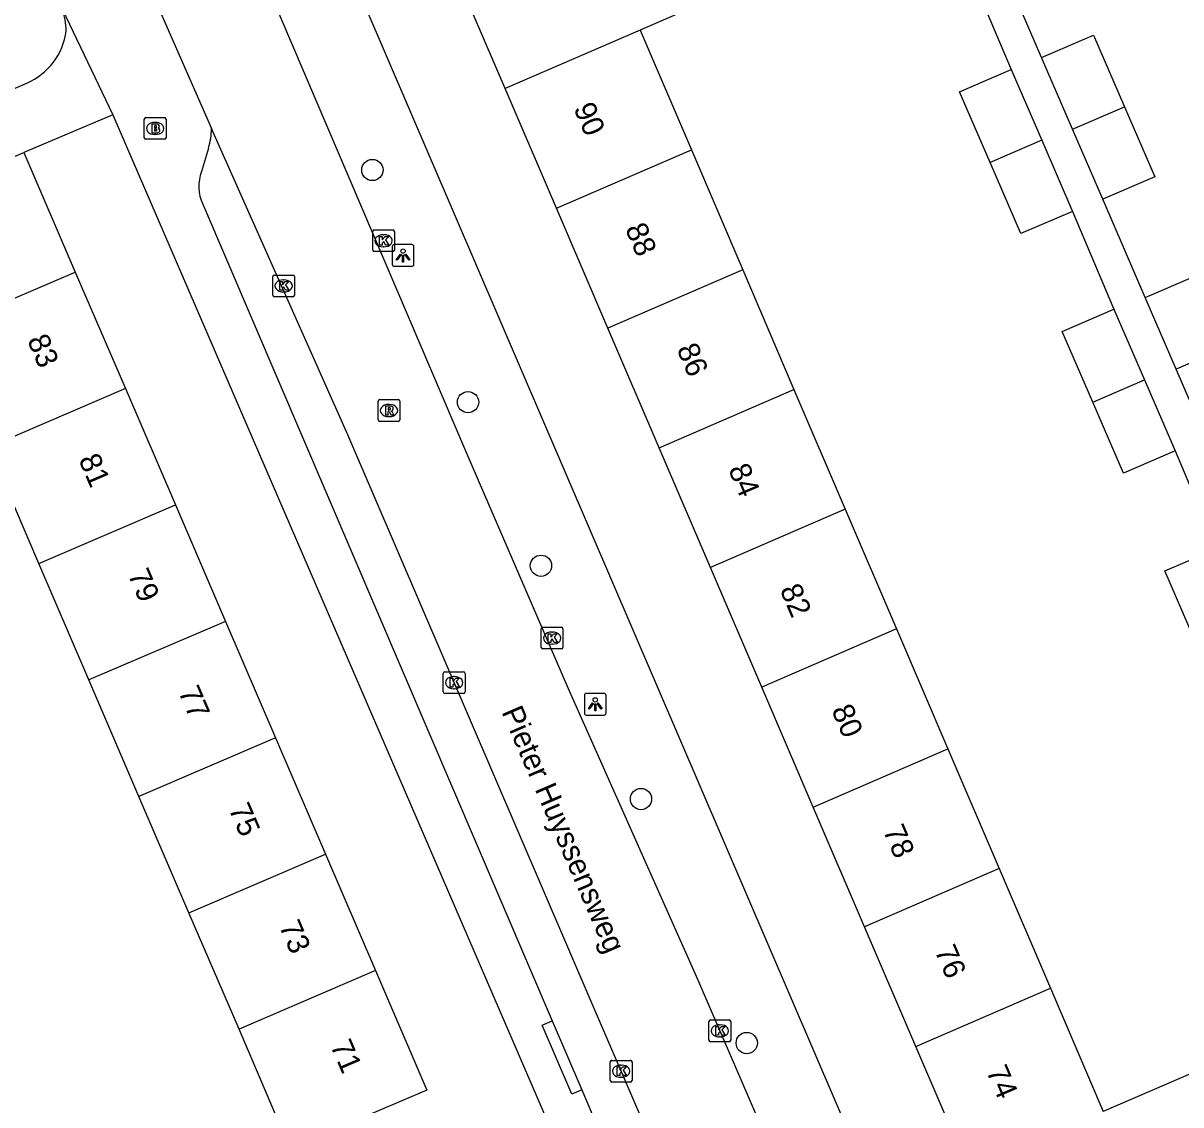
# Model space of a CAD drawing. Extents: x 159353 to 160616, y 385893 to 387321.
# Drawn here: x 159638.3 to 159691.6, y 386358.8 to 386408.6 of the extents above; entities that cross this region are included whole.
import ezdxf

# ---------------------------------------------------------------- set-up
doc = ezdxf.new("R2010")
doc.units = 0
for name, color, linetype in [('IMGEO_Boom', 7, 'Continuous'), ('IMGEO_Brandkraan', 7, 'Continuous'), ('IMGEO_Kolk', 7, 'Continuous'), ('IMGEO_Lichtpunt', 7, 'Continuous'), ('IMGEO_Openbare_ruimte_label', 7, 'Continuous'), ('IMGEO_Pand', 7, 'Continuous'), ('IMGEO_Pand_nummerreeks', 7, 'Continuous'), ('IMGEO_Rijbaan_lokaal_open', 7, 'Continuous'), ('IMGEO_Rioolput', 7, 'Continuous'), ('IMGEO_Voetpad_open', 7, 'Continuous')]:
    doc.layers.add(name, color=color, linetype=linetype)

msp = doc.modelspace()

# ---------------------------------------------------------------- linework, layer by layer
at = {"layer": 'IMGEO_Boom'}
for centre in [(159654.404, 386401.84), (159658.804, 386391.157), (159662.157, 386383.63), (159666.757, 386372.899), (159671.622, 386361.672)]:
    msp.add_circle(centre, 0.489, dxfattribs=at)
at = {"layer": 'IMGEO_Brandkraan'}
for p, q in [((159643.914, 386403.325), (159643.914, 386404.177)), ((159643.989, 386404.251), (159644.841, 386404.251)), ((159644.402, 386404.031), (159644.427, 386404.031)), ((159644.915, 386404.177), (159644.915, 386403.325)), ((159644.425, 386403.471), (159644.4, 386403.471)), ((159644.841, 386403.251), (159643.989, 386403.251))]:
    msp.add_line(p, q, dxfattribs=at)
for points in [[(159643.914, 386403.325), (159643.914, 386404.177)], [(159643.989, 386404.251), (159644.841, 386404.251)], [(159644.262, 386403.951), (159644.262, 386403.551), (159644.475, 386403.551)], [(159644.493, 386403.951), (159644.262, 386403.951)], [(159644.915, 386404.177), (159644.915, 386403.325)], [(159644.441, 386403.87), (159644.387, 386403.87), (159644.387, 386403.794)], [(159644.387, 386403.794), (159644.44, 386403.794)], [(159644.449, 386403.718), (159644.387, 386403.718), (159644.387, 386403.637)], [(159644.387, 386403.637), (159644.449, 386403.637)], [(159644.841, 386403.251), (159643.989, 386403.251)]]:
    msp.add_lwpolyline(points, dxfattribs=at)
for centre, radius, start, end in [((159643.991, 386404.175), 0.0765, 91.552, 178.448), ((159643.991, 386404.175), 0.0765, 91.552, 178.448), ((159644.497, 386403.806), 0.145, 59.4692, 91.5367), ((159644.522, 386403.853), 0.0922, 285.5137, 58.1501), ((159644.839, 386404.175), 0.0765, 1.552, 88.448), ((159644.839, 386404.175), 0.0765, 1.552, 88.448), ((159644.442, 386403.832), 0.0379, 267.8285, 90.9355), ((159644.45, 386403.677), 0.0404, 269.8759, 90.5077), ((159644.481, 386403.802), 0.251, 268.6676, 293.5347), ((159644.527, 386403.661), 0.105, 301.3115, 78.989), ((159643.991, 386403.327), 0.0765, 181.552, 268.448), ((159643.991, 386403.327), 0.0765, 181.552, 268.448), ((159644.839, 386403.327), 0.0765, 271.552, 358.448), ((159644.839, 386403.327), 0.0765, 271.552, 358.448)]:
    msp.add_arc(centre, radius, start, end, dxfattribs=at)
for centre, major_axis, ratio, start_param, end_param in [((159644.401, 386403.751), (-0.387, 0.002), 0.722429, 4.712389, 7.853982), ((159644.426, 386403.751), (-0.39, 0.002), 0.717154, 1.570796, 4.712389)]:
    msp.add_ellipse(centre, major_axis=major_axis, ratio=ratio, start_param=start_param, end_param=end_param, dxfattribs=at)
at = {"layer": 'IMGEO_Kolk'}
for p, q in [((159654.493, 386399.083), (159655.345, 386399.083)), ((159654.418, 386398.157), (159654.418, 386399.009)), ((159654.906, 386398.863), (159654.931, 386398.863)), ((159655.419, 386399.009), (159655.419, 386398.157)), ((159655.345, 386398.083), (159654.493, 386398.083)), ((159654.929, 386398.303), (159654.904, 386398.303)), ((159649.898, 386397.006), (159650.75, 386397.006)), ((159649.823, 386396.08), (159649.823, 386396.932)), ((159650.311, 386396.786), (159650.336, 386396.786)), ((159650.824, 386396.932), (159650.824, 386396.08)), ((159650.75, 386396.006), (159649.898, 386396.006)), ((159650.334, 386396.226), (159650.309, 386396.226)), ((159662.169, 386379.877), (159662.169, 386380.729)), ((159662.244, 386380.803), (159663.096, 386380.803)), ((159662.657, 386380.583), (159662.682, 386380.583)), ((159663.17, 386380.729), (159663.17, 386379.877)), ((159662.68, 386380.023), (159662.655, 386380.023)), ((159663.096, 386379.803), (159662.244, 386379.803)), ((159657.664, 386377.827), (159657.664, 386378.679)), ((159657.739, 386378.753), (159658.591, 386378.753)), ((159658.152, 386378.533), (159658.177, 386378.533)), ((159658.665, 386378.679), (159658.665, 386377.827)), ((159658.175, 386377.973), (159658.15, 386377.973)), ((159658.591, 386377.753), (159657.739, 386377.753)), ((159669.884, 386361.808), (159669.884, 386362.66)), ((159669.959, 386362.734), (159670.811, 386362.734)), ((159670.372, 386362.514), (159670.397, 386362.514)), ((159670.885, 386362.66), (159670.885, 386361.808)), ((159670.395, 386361.954), (159670.37, 386361.954)), ((159670.811, 386361.734), (159669.959, 386361.734)), ((159665.346, 386359.952), (159665.346, 386360.804)), ((159665.421, 386360.878), (159666.273, 386360.878)), ((159666.347, 386360.804), (159666.347, 386359.952)), ((159665.834, 386360.658), (159665.859, 386360.658)), ((159666.273, 386359.878), (159665.421, 386359.878)), ((159665.857, 386360.098), (159665.832, 386360.098))]:
    msp.add_line(p, q, dxfattribs=at)
for points in [[(159654.493, 386399.083), (159655.345, 386399.083)], [(159654.418, 386398.157), (159654.418, 386399.009)], [(159654.739, 386398.783), (159654.862, 386398.783), (159654.862, 386398.632), (159654.992, 386398.783), (159655.156, 386398.783), (159655.01, 386398.632), (159655.163, 386398.383), (159655.011, 386398.383), (159654.926, 386398.547), (159654.862, 386398.48), (159654.862, 386398.383), (159654.739, 386398.383), (159654.739, 386398.783)], [(159655.419, 386399.009), (159655.419, 386398.157)], [(159655.345, 386398.083), (159654.493, 386398.083)], [(159649.898, 386397.006), (159650.75, 386397.006)], [(159649.823, 386396.08), (159649.823, 386396.932)], [(159650.144, 386396.706), (159650.267, 386396.706), (159650.267, 386396.555), (159650.397, 386396.706), (159650.561, 386396.706), (159650.415, 386396.555), (159650.568, 386396.306), (159650.416, 386396.306), (159650.331, 386396.47), (159650.267, 386396.403), (159650.267, 386396.306), (159650.144, 386396.306), (159650.144, 386396.706)], [(159650.824, 386396.932), (159650.824, 386396.08)], [(159650.75, 386396.006), (159649.898, 386396.006)], [(159662.169, 386379.877), (159662.169, 386380.729)], [(159662.244, 386380.803), (159663.096, 386380.803)], [(159662.49, 386380.503), (159662.613, 386380.503), (159662.613, 386380.352), (159662.743, 386380.503), (159662.907, 386380.503), (159662.761, 386380.352), (159662.914, 386380.103), (159662.762, 386380.103), (159662.677, 386380.267), (159662.613, 386380.2), (159662.613, 386380.103), (159662.49, 386380.103), (159662.49, 386380.503)], [(159663.17, 386380.729), (159663.17, 386379.877)], [(159663.096, 386379.803), (159662.244, 386379.803)], [(159657.664, 386377.827), (159657.664, 386378.679)], [(159657.739, 386378.753), (159658.591, 386378.753)], [(159657.985, 386378.453), (159658.108, 386378.453), (159658.108, 386378.302), (159658.238, 386378.453), (159658.402, 386378.453), (159658.256, 386378.302), (159658.409, 386378.053), (159658.257, 386378.053), (159658.172, 386378.217), (159658.108, 386378.15), (159658.108, 386378.053), (159657.985, 386378.053), (159657.985, 386378.453)], [(159658.665, 386378.679), (159658.665, 386377.827)], [(159658.591, 386377.753), (159657.739, 386377.753)], [(159669.884, 386361.808), (159669.884, 386362.66)], [(159669.959, 386362.734), (159670.811, 386362.734)], [(159670.205, 386362.434), (159670.328, 386362.434), (159670.328, 386362.283), (159670.458, 386362.434), (159670.622, 386362.434), (159670.476, 386362.283), (159670.629, 386362.034), (159670.477, 386362.034), (159670.392, 386362.198), (159670.328, 386362.131), (159670.328, 386362.034), (159670.205, 386362.034), (159670.205, 386362.434)], [(159670.885, 386362.66), (159670.885, 386361.808)], [(159670.811, 386361.734), (159669.959, 386361.734)], [(159665.346, 386359.952), (159665.346, 386360.804)], [(159665.421, 386360.878), (159666.273, 386360.878)], [(159666.347, 386360.804), (159666.347, 386359.952)], [(159665.667, 386360.578), (159665.79, 386360.578), (159665.79, 386360.427), (159665.92, 386360.578), (159666.084, 386360.578), (159665.938, 386360.427), (159666.091, 386360.178), (159665.939, 386360.178), (159665.854, 386360.342), (159665.79, 386360.275), (159665.79, 386360.178), (159665.667, 386360.178), (159665.667, 386360.578)], [(159666.273, 386359.878), (159665.421, 386359.878)]]:
    msp.add_lwpolyline(points, dxfattribs=at)
for centre, start, end in [((159654.495, 386399.007), 91.552, 178.448), ((159654.495, 386399.007), 91.552, 178.448), ((159655.343, 386399.007), 1.552, 88.448), ((159655.343, 386399.007), 1.552, 88.448), ((159654.495, 386398.159), 181.552, 268.448), ((159654.495, 386398.159), 181.552, 268.448), ((159655.343, 386398.159), 271.552, 358.448), ((159655.343, 386398.159), 271.552, 358.448), ((159649.9, 386396.93), 91.552, 178.448), ((159649.9, 386396.93), 91.552, 178.448), ((159650.748, 386396.93), 1.552, 88.448), ((159650.748, 386396.93), 1.552, 88.448), ((159649.9, 386396.082), 181.552, 268.448), ((159649.9, 386396.082), 181.552, 268.448), ((159650.748, 386396.082), 271.552, 358.448), ((159650.748, 386396.082), 271.552, 358.448), ((159662.246, 386380.727), 91.552, 178.448), ((159662.246, 386380.727), 91.552, 178.448), ((159663.094, 386380.727), 1.552, 88.448), ((159663.094, 386380.727), 1.552, 88.448), ((159662.246, 386379.879), 181.552, 268.448), ((159662.246, 386379.879), 181.552, 268.448), ((159663.094, 386379.879), 271.552, 358.448), ((159663.094, 386379.879), 271.552, 358.448), ((159657.741, 386378.677), 91.552, 178.448), ((159657.741, 386378.677), 91.552, 178.448), ((159658.589, 386378.677), 1.552, 88.448), ((159658.589, 386378.677), 1.552, 88.448), ((159657.741, 386377.829), 181.552, 268.448), ((159657.741, 386377.829), 181.552, 268.448), ((159658.589, 386377.829), 271.552, 358.448), ((159658.589, 386377.829), 271.552, 358.448), ((159669.961, 386362.658), 91.552, 178.448), ((159669.961, 386362.658), 91.552, 178.448), ((159670.809, 386362.658), 1.552, 88.448), ((159670.809, 386362.658), 1.552, 88.448), ((159669.961, 386361.81), 181.552, 268.448), ((159669.961, 386361.81), 181.552, 268.448), ((159670.809, 386361.81), 271.552, 358.448), ((159670.809, 386361.81), 271.552, 358.448), ((159665.423, 386360.802), 91.552, 178.448), ((159665.423, 386360.802), 91.552, 178.448), ((159666.271, 386360.802), 1.552, 88.448), ((159666.271, 386360.802), 1.552, 88.448), ((159665.423, 386359.954), 181.552, 268.448), ((159665.423, 386359.954), 181.552, 268.448), ((159666.271, 386359.954), 271.552, 358.448), ((159666.271, 386359.954), 271.552, 358.448)]:
    msp.add_arc(centre, 0.0765, start, end, dxfattribs=at)
for centre, major_axis, ratio, start_param, end_param in [((159654.905, 386398.583), (-0.387, 0.002), 0.722429, 4.712389, 7.853982), ((159654.93, 386398.583), (-0.39, 0.002), 0.717154, 1.570796, 4.712389), ((159650.31, 386396.506), (-0.387, 0.002), 0.722429, 4.712389, 7.853982), ((159650.335, 386396.506), (-0.39, 0.002), 0.717154, 1.570796, 4.712389), ((159662.656, 386380.303), (-0.387, 0.002), 0.722429, 4.712389, 7.853982), ((159662.681, 386380.303), (-0.39, 0.002), 0.717154, 1.570796, 4.712389), ((159658.151, 386378.253), (-0.387, 0.002), 0.722429, 4.712389, 7.853982), ((159658.176, 386378.253), (-0.39, 0.002), 0.717154, 1.570796, 4.712389), ((159670.371, 386362.234), (-0.387, 0.002), 0.722429, 4.712389, 7.853982), ((159670.396, 386362.234), (-0.39, 0.002), 0.717154, 1.570796, 4.712389), ((159665.833, 386360.378), (-0.387, 0.002), 0.722429, 4.712389, 7.853982), ((159665.858, 386360.378), (-0.39, 0.002), 0.717154, 1.570796, 4.712389)]:
    msp.add_ellipse(centre, major_axis=major_axis, ratio=ratio, start_param=start_param, end_param=end_param, dxfattribs=at)
at = {"layer": 'IMGEO_Lichtpunt'}
for p, q in [((159655.317, 386398.31), (159655.317, 386397.503)), ((159655.317, 386398.31), (159655.317, 386397.503)), ((159656.219, 386398.405), (159655.411, 386398.405)), ((159656.219, 386398.405), (159655.411, 386398.405)), ((159656.313, 386397.503), (159656.313, 386398.31)), ((159656.313, 386397.503), (159656.313, 386398.31)), ((159655.411, 386397.409), (159656.219, 386397.409)), ((159655.411, 386397.409), (159656.219, 386397.409)), ((159664.154, 386377.664), (159664.154, 386376.857)), ((159664.154, 386377.664), (159664.154, 386376.857)), ((159665.056, 386377.759), (159664.248, 386377.759)), ((159665.056, 386377.759), (159664.248, 386377.759)), ((159665.15, 386376.857), (159665.15, 386377.664)), ((159665.15, 386376.857), (159665.15, 386377.664)), ((159664.248, 386376.763), (159665.056, 386376.763)), ((159664.248, 386376.763), (159665.056, 386376.763))]:
    msp.add_line(p, q, dxfattribs=at)
for points in [[(159655.691, 386397.974), (159655.73, 386397.946), (159655.542, 386397.684), (159655.504, 386397.711), (159655.691, 386397.974)], [(159655.793, 386397.926), (159655.84, 386397.926), (159655.84, 386397.604), (159655.793, 386397.604), (159655.793, 386397.926)], [(159655.903, 386397.946), (159655.941, 386397.973), (159656.128, 386397.711), (159656.089, 386397.683), (159655.903, 386397.946)], [(159664.528, 386377.328), (159664.567, 386377.3), (159664.379, 386377.038), (159664.341, 386377.065), (159664.528, 386377.328)], [(159664.63, 386377.28), (159664.677, 386377.28), (159664.677, 386376.958), (159664.63, 386376.958), (159664.63, 386377.28)], [(159664.74, 386377.3), (159664.778, 386377.327), (159664.965, 386377.065), (159664.926, 386377.037), (159664.74, 386377.3)]]:
    msp.add_lwpolyline(points, dxfattribs=at)
for centre in [(159655.816, 386398.108), (159664.653, 386377.462)]:
    msp.add_circle(centre, 0.0994, dxfattribs=at)
for centre, start, end in [((159655.411, 386398.31), 90, 180), ((159655.411, 386398.31), 90, 180), ((159656.219, 386398.31), 0, 90), ((159656.219, 386398.31), 0, 90), ((159655.411, 386397.503), 180, 270), ((159655.411, 386397.503), 180, 270), ((159656.219, 386397.503), 270, 0), ((159656.219, 386397.503), 270, 360), ((159664.248, 386377.664), 90, 180), ((159664.248, 386377.664), 90, 180), ((159665.056, 386377.664), 0, 90), ((159665.056, 386377.664), 0, 90), ((159664.248, 386376.857), 180, 270), ((159664.248, 386376.857), 180, 270), ((159665.056, 386376.857), 270, 0), ((159665.056, 386376.857), 270, 360)]:
    msp.add_arc(centre, 0.0946, start, end, dxfattribs=at)
at = {"layer": 'IMGEO_Pand'}
for points in [[(159666.994, 386415.089), (159669.434, 386409.449), (159666.714, 386408.272)], [(159660.51, 386405.587), (159658.09, 386411.236)], [(159666.714, 386408.272), (159660.51, 386405.587)], [(159666.714, 386408.272), (159669.073, 386402.762)], [(159685.183, 386407.014), (159687.567, 386408.042), (159688.989, 386404.745)], [(159686.607, 386403.715), (159685.183, 386407.014)], [(159682.816, 386402.178), (159681.412, 386405.433), (159683.787, 386406.457)], [(159683.787, 386406.457), (159685.19, 386403.205)], [(159662.871, 386400.077), (159660.51, 386405.587)], [(159686.607, 386403.715), (159688.989, 386404.745)], [(159688.989, 386404.745), (159690.381, 386401.52), (159687.997, 386400.492)], [(159687.997, 386400.492), (159686.607, 386403.715)], [(159685.19, 386403.205), (159682.816, 386402.178)], [(159685.19, 386403.205), (159686.601, 386399.935)], [(159632.112, 386399.947), (159638.383, 386402.64)], [(159638.383, 386402.64), (159640.743, 386397.144)], [(159662.871, 386400.077), (159669.073, 386402.762)], [(159669.073, 386402.762), (159671.433, 386397.252)], [(159686.601, 386399.935), (159684.226, 386398.911), (159682.816, 386402.178)], [(159665.231, 386394.568), (159662.871, 386400.077)], [(159634.471, 386394.451), (159640.743, 386397.144)], [(159640.743, 386397.144), (159643.044, 386391.788)], [(159671.433, 386397.252), (159665.231, 386394.568)], [(159671.433, 386397.252), (159673.793, 386391.741)], [(159689.946, 386395.967), (159692.33, 386396.995), (159693.752, 386393.7)], [(159691.369, 386392.669), (159689.946, 386395.967)], [(159687.535, 386391.16), (159686.131, 386394.413), (159688.506, 386395.437)], [(159688.506, 386395.437), (159689.908, 386392.187)], [(159667.592, 386389.058), (159665.231, 386394.568)], [(159693.752, 386393.7), (159691.369, 386392.669)], [(159687.535, 386391.16), (159689.908, 386392.187)], [(159689.908, 386392.187), (159691.32, 386388.915)], [(159692.76, 386389.445), (159691.369, 386392.669)], [(159643.044, 386391.788), (159636.771, 386389.094)], [(159643.044, 386391.788), (159645.345, 386386.431)], [(159667.592, 386389.058), (159673.793, 386391.741)], [(159673.793, 386391.741), (159676.152, 386386.232)], [(159691.32, 386388.915), (159688.945, 386387.891), (159687.535, 386391.16)], [(159639.071, 386383.736), (159636.771, 386389.094)], [(159669.952, 386383.548), (159667.592, 386389.058)], [(159639.071, 386383.736), (159645.345, 386386.431)], [(159645.345, 386386.431), (159647.646, 386381.074)], [(159676.152, 386386.232), (159669.952, 386383.548)], [(159676.152, 386386.232), (159678.511, 386380.722)], [(159692.254, 386380.138), (159690.85, 386383.393), (159693.225, 386384.417)], [(159641.371, 386378.38), (159639.071, 386383.736)], [(159672.312, 386378.04), (159669.952, 386383.548)], [(159647.646, 386381.074), (159641.371, 386378.38)], [(159647.646, 386381.074), (159649.946, 386375.718)], [(159678.511, 386380.722), (159672.312, 386378.04)], [(159678.511, 386380.722), (159680.871, 386375.212)], [(159643.671, 386373.022), (159641.371, 386378.38)], [(159674.673, 386372.53), (159672.312, 386378.04)], [(159649.946, 386375.718), (159643.671, 386373.022)], [(159649.946, 386375.718), (159652.247, 386370.361)], [(159674.673, 386372.53), (159680.871, 386375.212)], [(159680.871, 386375.212), (159683.231, 386369.701)], [(159645.971, 386367.665), (159643.671, 386373.022)], [(159677.034, 386367.019), (159674.673, 386372.53)], [(159645.971, 386367.665), (159652.247, 386370.361)], [(159652.247, 386370.361), (159654.548, 386365.004)], [(159683.231, 386369.701), (159677.034, 386367.019)], [(159683.231, 386369.701), (159685.59, 386364.191)], [(159648.271, 386362.308), (159645.971, 386367.665)], [(159679.394, 386361.509), (159677.034, 386367.019)], [(159654.548, 386365.004), (159656.908, 386359.509), (159652.314, 386357.536), (159650.63, 386356.812), (159648.271, 386362.308)], [(159654.548, 386365.004), (159648.271, 386362.308)], [(159679.394, 386361.509), (159685.59, 386364.191)], [(159685.59, 386364.191), (159688.018, 386358.522)], [(159681.812, 386355.866), (159679.394, 386361.509)]]:
    msp.add_lwpolyline(points, dxfattribs=at)
at = {"layer": 'IMGEO_Rijbaan_lokaal_open'}
for points in [[(159646.44, 386417.646), (159658.694, 386388.914), (159663.41, 386377.978), (159669.357, 386364.619), (159674.395, 386352.921), (159680.586, 386338.124), (159685.711, 386326.516)], [(159641.964, 386415.245), (159647, 386403.746)], [(159681.53, 386324.098), (159679.223, 386329.328), (159664.516, 386363.471), (159653.271, 386389.647), (159647, 386403.746)]]:
    msp.add_lwpolyline(points, dxfattribs=at)
at = {"layer": 'IMGEO_Rioolput'}
for p, q in [((159654.666, 386390.347), (159654.666, 386391.199)), ((159654.741, 386391.273), (159655.593, 386391.273)), ((159655.667, 386391.199), (159655.667, 386390.347)), ((159655.154, 386391.053), (159655.179, 386391.053)), ((159655.593, 386390.273), (159654.741, 386390.273)), ((159655.177, 386390.493), (159655.152, 386390.493))]:
    msp.add_line(p, q, dxfattribs=at)
for points in [[(159654.666, 386390.347), (159654.666, 386391.199)], [(159654.741, 386391.273), (159655.593, 386391.273)], [(159655.667, 386391.199), (159655.667, 386390.347)], [(159655.255, 386390.971), (159655.003, 386390.973), (159655.003, 386390.573)], [(159655.003, 386390.573), (159655.127, 386390.573), (159655.127, 386390.735), (159655.138, 386390.735)], [(159655.181, 386390.892), (159655.127, 386390.892), (159655.127, 386390.811)], [(159655.127, 386390.811), (159655.179, 386390.811)], [(159655.185, 386390.706), (159655.256, 386390.573), (159655.396, 386390.573), (159655.331, 386390.699)], [(159655.593, 386390.273), (159654.741, 386390.273)]]:
    msp.add_lwpolyline(points, dxfattribs=at)
for centre, radius, start, end in [((159654.743, 386391.197), 0.0765, 91.552, 178.448), ((159654.743, 386391.197), 0.0765, 91.552, 178.448), ((159655.591, 386391.197), 0.0765, 1.552, 88.448), ((159655.591, 386391.197), 0.0765, 1.552, 88.448), ((159655.137, 386390.682), 0.0533, 26.0293, 88.6989), ((159655.163, 386391), 0.19, 274.7715, 282.9687), ((159655.187, 386390.796), 0.0964, 77.0061, 93.1865), ((159655.201, 386390.853), 0.0378, 276.6634, 79.6772), ((159655.254, 386390.861), 0.109, 350.3612, 89.416), ((159655.252, 386390.861), 0.112, 277.5842, 350.9817), ((159655.236, 386390.646), 0.108, 29.5134, 73.7905), ((159654.743, 386390.349), 0.0765, 181.552, 268.448), ((159654.743, 386390.349), 0.0765, 181.552, 268.448), ((159655.591, 386390.349), 0.0765, 271.552, 358.448), ((159655.591, 386390.349), 0.0765, 271.552, 358.448)]:
    msp.add_arc(centre, radius, start, end, dxfattribs=at)
for centre, major_axis, ratio, start_param, end_param in [((159655.153, 386390.773), (-0.387, 0.002), 0.722429, 4.712389, 7.853982), ((159655.178, 386390.773), (-0.39, 0.002), 0.717154, 1.570796, 4.712389)]:
    msp.add_ellipse(centre, major_axis=major_axis, ratio=ratio, start_param=start_param, end_param=end_param, dxfattribs=at)
at = {"layer": 'IMGEO_Voetpad_open'}
for points in [[(159685.183, 386407.014), (159683.234, 386411.539)], [(159681.882, 386410.955), (159683.787, 386406.457)], [(159640.145, 386409.246), (159642.474, 386404.373)], [(159677.79, 386354.14), (159654.031, 386409.485)], [(159632.4, 386403.215), (159638.517, 386405.84)], [(159642.474, 386404.373), (159638.383, 386402.64)], [(159642.474, 386404.373), (159662.319, 386358.392)], [(159646.871, 386402.849), (159646.55, 386401.775)], [(159646.602, 386400.263), (159662.676, 386362.691)], [(159689.946, 386395.967), (159687.997, 386400.492)], [(159686.601, 386399.935), (159688.506, 386395.437)], [(159691.32, 386388.915), (159693.225, 386384.417)], [(159700.758, 386366.874), (159701.797, 386364.467), (159688.018, 386358.522)], [(159664.032, 386359.521), (159663.573, 386359.323), (159662.217, 386362.493), (159662.676, 386362.691)], [(159662.676, 386362.691), (159664.032, 386359.521)], [(159664.032, 386359.521), (159664.771, 386357.792)]]:
    msp.add_lwpolyline(points, dxfattribs=at)
for centre, radius, start, end in [((159637.092, 386408.187), 3.231, 0.8086, 19.1235), ((159637.324, 386408.618), 3.023, 293.2352, 352.681), ((159644.032, 386403.715), 2.968, 343.0346, 0.5979), ((159648.406, 386401.082), 1.981, 159.5256, 204.4138)]:
    msp.add_arc(centre, radius, start, end, dxfattribs=at)

# ---------------------------------------------------------------- texts
at = {"layer": 'IMGEO_Openbare_ruimte_label'}
msp.add_text('Pieter Huyssensweg', height=1, rotation=293.334, dxfattribs=at).set_placement((159660.33, 386376.912))
at = {"layer": 'IMGEO_Pand_nummerreeks'}
for s, rotation, p in [('90', 293.1916, (159663.64, 386404.68)), ('88', 293.1916, (159666.012, 386399.143)), ('83', 293.2438, (159638.517, 386394.018)), ('86', 293.1916, (159668.383, 386393.609)), ('81', 293.2438, (159640.877, 386388.523)), ('84', 293.1916, (159670.756, 386388.072)), ('79', 293.2438, (159643.148, 386383.236)), ('82', 293.1916, (159673.127, 386382.538)), ('77', 293.2438, (159645.464, 386377.844)), ('80', 293.1916, (159675.501, 386376.995)), ('75', 293.2438, (159647.779, 386372.453)), ('78', 293.1916, (159677.873, 386371.458)), ('73', 293.2438, (159650.095, 386367.062)), ('76', 293.1916, (159680.244, 386365.924)), ('71', 293.2438, (159652.456, 386361.566)), ('74', 293.1916, (159682.617, 386360.387))]:
    msp.add_text(s, height=1, rotation=rotation, dxfattribs=at).set_placement(p)

doc.saveas('drawing.dxf')
